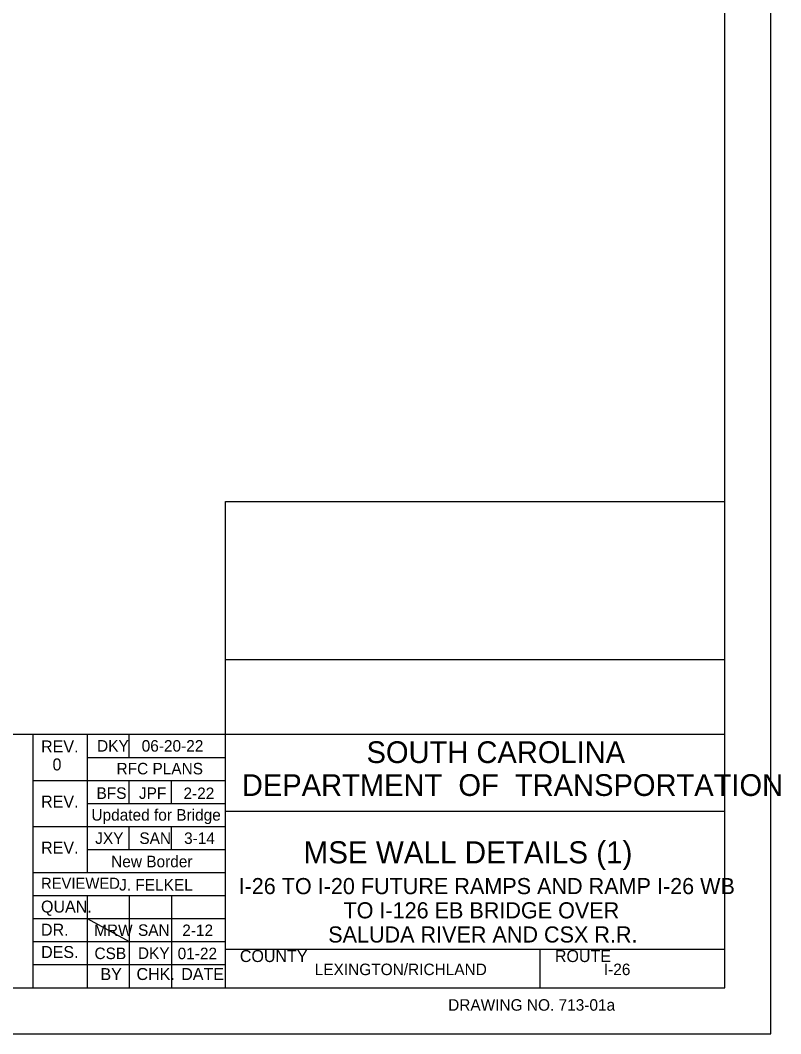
# Model space of a CAD drawing. Extents: x -133.1 to -97, y -1.7 to 20.3.
# Drawn here: x -105.28 to -97.03, y -1.69 to 9.31 of the extents above; entities that cross this region are included whole.
import ezdxf

# ---------------------------------------------------------------- set-up
doc = ezdxf.new("R2010")
doc.units = 0
for name, color, linetype in [('BR_BORDER LINES', 7, 'Continuous'), ('BR_TEXT', 7, 'Continuous'), ('Level 31', 7, 'Continuous')]:
    doc.layers.add(name, color=color, linetype=linetype)

msp = doc.modelspace()

# ---------------------------------------------------------------- linework, layer by layer
at = {"layer": 'BR_BORDER LINES'}
for p, q in [((-97.642, -1.191), (-97.642, 19.809)), ((-103.058, -1.191), (-103.058, 4.086)), ((-103.058, 4.086), (-97.642, 4.086)), ((-103.058, 2.371), (-97.642, 2.371)), ((-110.507, 1.559), (-105.142, 1.559)), ((-105.142, -1.191), (-105.142, 1.559)), ((-105.142, 1.559), (-97.642, 1.559)), ((-104.559, 1.559), (-104.559, 0.059)), ((-104.1, 1.309), (-104.1, 1.559)), ((-104.559, 1.309), (-103.058, 1.309)), ((-105.142, 1.059), (-103.058, 1.059)), ((-104.1, 0.809), (-104.1, 1.059)), ((-103.642, 0.809), (-103.642, 1.059)), ((-104.559, 0.809), (-103.058, 0.809)), ((-103.058, 0.726), (-103.058, 0.726)), ((-103.058, 0.726), (-97.641, 0.726)), ((-105.142, 0.559), (-103.058, 0.559)), ((-104.1, 0.309), (-104.1, 0.559)), ((-103.642, 0.309), (-103.642, 0.559)), ((-104.559, 0.309), (-103.058, 0.309)), ((-105.142, 0.059), (-103.058, 0.059)), ((-105.142, -0.191), (-103.058, -0.191)), ((-104.559, -0.191), (-104.559, -1.191)), ((-104.1, -0.191), (-104.1, -1.191)), ((-103.642, -0.191), (-103.642, -1.191)), ((-105.142, -0.441), (-103.058, -0.441)), ((-105.142, -0.691), (-103.058, -0.691)), ((-103.058, -0.774), (-97.642, -0.774)), ((-102.961, -0.774), (-97.642, -0.774)), ((-99.642, -1.191), (-99.642, -0.774)), ((-105.142, -0.941), (-103.058, -0.941)), ((-131.308, -1.191), (-97.642, -1.191))]:
    msp.add_line(p, q, dxfattribs=at)
at = {"layer": 'Level 31'}
for p, q in [((-100.35, 0.285), (-100.35, 0.285)), ((-104.559, -0.441), (-104.1, -0.691))]:
    msp.add_line(p, q, dxfattribs=at)
msp.add_lwpolyline([(-133.141, -1.691), (-97.141, -1.691), (-97.141, 20.309), (-133.141, 20.309)], close=True, dxfattribs=at)

# ---------------------------------------------------------------- texts
at = {"layer": 'BR_TEXT'}
for s, height, p in [('REV.', 0.13, (-105.057, 1.362)), ('DKY', 0.125, (-104.45, 1.371)), ('06-20-22', 0.125, (-103.966, 1.371)), ('SOUTH CAROLINA', 0.23587, (-101.527, 1.247)), ('0', 0.13, (-104.933, 1.167)), ('RFC PLANS', 0.125, (-104.239, 1.124)), ('DEPARTMENT  OF  TRANSPORTATION', 0.23587, (-102.879, 0.89)), ('REV.', 0.13, (-105.057, 0.764)), ('BFS', 0.125, (-104.456, 0.858)), ('JPF', 0.125, (-103.996, 0.858)), ('2-22', 0.125, (-103.513, 0.856)), ('Updated for Bridge', 0.125, (-104.511, 0.622)), ('JXY', 0.125, (-104.47, 0.369)), ('SAN', 0.125, (-103.991, 0.369)), ('3-14', 0.125, (-103.506, 0.369)), ('REV.', 0.13, (-105.057, 0.264)), ('MSE WALL DETAILS (1)', 0.24, (-102.21, 0.158)), ('New Border', 0.125, (-104.297, 0.116)), ('REVIEWED', 0.12, (-105.058, -0.118)), ('I-26 TO I-20 FUTURE RAMPS AND RAMP I-26 WB', 0.175, (-102.915, -0.176)), ('J. FELKEL', 0.125, (-104.211, -0.137)), ('QUAN.', 0.13, (-105.058, -0.376)), ('TO I-126 EB BRIDGE OVER', 0.175, (-101.777, -0.439)), ('DR.', 0.13, (-105.058, -0.627)), ('2-12', 0.125, (-103.526, -0.631)), ('SALUDA RIVER AND CSX R.R.', 0.175, (-101.943, -0.701)), ('DES.', 0.13, (-105.057, -0.869)), ('01-22', 0.125, (-103.576, -0.882)), ('COUNTY', 0.13, (-102.901, -0.913)), ('ROUTE', 0.13, (-99.484, -0.913)), ('BY', 0.13, (-104.413, -1.109)), ('CHK.', 0.13, (-104.022, -1.108)), ('DATE', 0.13, (-103.537, -1.108)), ('LEXINGTON/RICHLAND', 0.12499, (-102.089, -1.055)), ('I-26', 0.125, (-98.953, -1.055)), ('DRAWING NO. 713-01a', 0.125, (-100.642, -1.441))]:
    msp.add_text(s, height=height, dxfattribs=at).set_placement(p)
for s, p in [('MRW', (-104.482, -0.631)), ('SAN', (-104.006, -0.629)), ('CSB', (-104.478, -0.881)), ('CSB', (-104.478, -0.881)), ('DKY', (-104.007, -0.879)), ('DKY', (-104.007, -0.879))]:
    msp.add_text(s, height=0.125, rotation=360, dxfattribs=at).set_placement(p)

doc.saveas('drawing.dxf')
